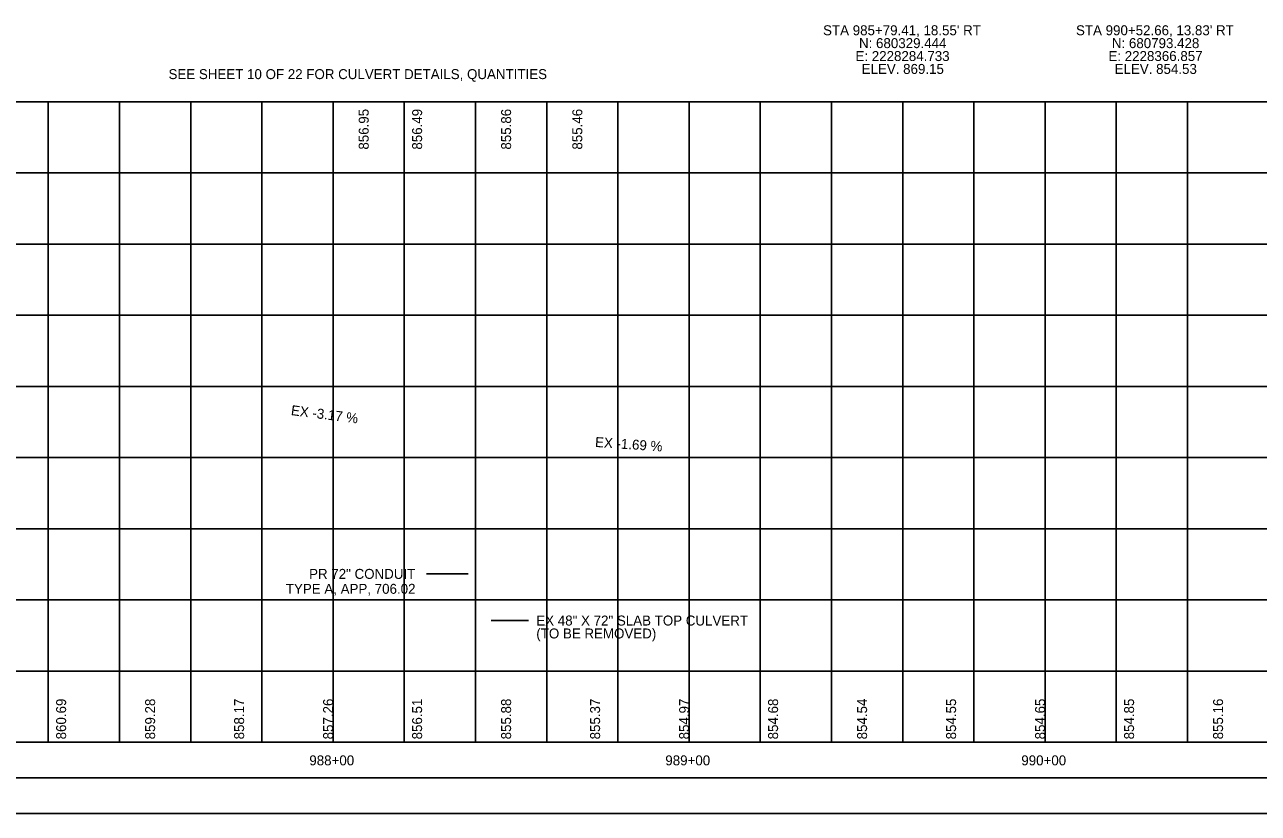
# Model space of a CAD drawing. Extents: x 0 to 905, y 0 to 440.
# Drawn here: x 207.4 to 553.9, y 0 to 221.7 of the extents above; entities that cross this region are included whole.
import ezdxf

# ---------------------------------------------------------------- set-up
doc = ezdxf.new("R2010")
doc.units = 0
for name, color, linetype in [('DR_X_Culvert', 7, 'Continuous'), ('GE_X_Alignment', 7, 'Continuous'), ('GE_X_Alignment_100_Cardinal_Points', 7, 'Continuous'), ('PF_X_Ground_Line', 7, 'Continuous'), ('TX_X_5', 7, 'Continuous'), ('XS_X_Pavt', 7, 'Continuous')]:
    doc.layers.add(name, color=color, linetype=linetype)

msp = doc.modelspace()

# ---------------------------------------------------------------- linework, layer by layer
at = {"layer": 'DR_X_Culvert'}
msp.add_lwpolyline([(0, 0), (680, 0), (680, 440), (0, 440)], close=True, dxfattribs=at)
at = {"layer": 'GE_X_Alignment'}
for p, q in [((514, 20), (514, 200)), ((534, 20), (534, 200)), ((331.92, 67.3), (320.24, 67.3))]:
    msp.add_line(p, q, dxfattribs=at)
at = {"layer": 'GE_X_Alignment_100_Cardinal_Points'}
msp.add_line((338.36, 54.19), (348.93, 54.19), dxfattribs=at)
at = {"layer": 'PF_X_Ground_Line'}
msp.add_lwpolyline([(30, 430), (670, 430), (670, 10), (30, 10)], close=True, dxfattribs=at)
at = {"layer": 'TX_X_5'}
for p, q in [((214, 20), (214, 200)), ((234, 20), (234, 200)), ((254, 20), (254, 200)), ((274, 20), (274, 200)), ((294, 20), (294, 200)), ((314, 20), (314, 200)), ((334, 20), (334, 200)), ((354, 20), (354, 200)), ((374, 20), (374, 200)), ((394, 20), (394, 200)), ((414, 20), (414, 200)), ((434, 20), (434, 200)), ((454, 20), (454, 200)), ((474, 20), (474, 200)), ((494, 20), (494, 200)), ((34, 180), (634, 180)), ((34, 160), (634, 160)), ((34, 140), (634, 140)), ((34, 120), (634, 120)), ((34, 100), (634, 100)), ((34, 80), (634, 80)), ((34, 60), (634, 60)), ((34, 40), (634, 40))]:
    msp.add_line(p, q, dxfattribs=at)
at = {"layer": 'XS_X_Pavt'}
for p, q in [((634, 200), (34, 200)), ((34, 20), (634, 20))]:
    msp.add_line(p, q, dxfattribs=at)

# ---------------------------------------------------------------- texts
at = {"layer": 'GE_X_Alignment'}
for s, p in [("STA 985+79.41, 18.55' RT", (431.64, 218.7)), ("STA 990+52.66, 13.83' RT", (502.69, 218.7)), ('N: 680329.444', (441.73, 215.08)), ('N: 680793.428', (512.77, 215.08)), ('E: 2228284.733', (440.74, 211.45)), ('E: 2228366.857', (511.8, 211.45)), ('SEE SHEET 10 OF 22 FOR CULVERT DETAILS, QUANTITIES', (247.77, 206.37)), ('ELEV. 869.15', (442.47, 207.83)), ('ELEV. 854.53', (513.53, 207.83)), ('PR 72" CONDUIT', (287.25, 65.9)), ('TYPE A, APP, 706.02', (280.72, 61.7))]:
    msp.add_text(s, height=2.8, dxfattribs=at).set_placement(p)
for s, rotation, p in [('856.95', 90, (304, 186.55)), ('856.49', 90, (319, 186.55)), ('855.86', 90, (344, 186.55)), ('855.46', 90, (364, 186.55)), ('EX -3.17 %', 352.7761, (282.05, 111.96)), ('EX -1.69 %', 356.1298, (367.51, 102.99))]:
    msp.add_text(s, height=2.8, rotation=rotation, dxfattribs=at).set_placement(p)
at = {"layer": 'GE_X_Alignment_100_Cardinal_Points'}
for s, p in [('EX 48" X 72" SLAB TOP CULVERT', (351.08, 52.79)), ('(TO BE REMOVED)', (351.08, 49.16)), ('988+00', (287.32, 13.49)), ('989+00', (387.32, 13.49)), ('990+00', (487.32, 13.49))]:
    msp.add_text(s, height=2.8, dxfattribs=at).set_placement(p)
for s, p in [('860.69', (219, 20.79)), ('859.28', (244, 20.79)), ('858.17', (269, 20.79)), ('857.26', (294, 20.79)), ('856.51', (319, 20.79)), ('855.88', (344, 20.79)), ('855.37', (369, 20.79)), ('854.97', (394, 20.79)), ('854.68', (419, 20.79)), ('854.54', (444, 20.79)), ('854.55', (469, 20.79)), ('854.65', (494, 20.79)), ('854.85', (519, 20.79)), ('855.16', (544, 20.79))]:
    msp.add_text(s, height=2.8, rotation=90, dxfattribs=at).set_placement(p)

doc.saveas('drawing.dxf')
